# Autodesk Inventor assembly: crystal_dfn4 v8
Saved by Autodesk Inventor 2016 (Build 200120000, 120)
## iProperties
Created: 2016-09
Part Number: crystal_dfn4 v8
Document SubType Name: Assembly
Designer: Administrator
Author: Administrator
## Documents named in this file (5)
- c:\worker\convert-fusion-aug-2016\tmp\job-1\19\output\files\b1646d38-3d95-4128-a552-c87d2d1b62c9\crystal_dfn4 v8.iam
- c:\worker\convert-fusion-aug-2016\tmp\job-1\19\output\files\b1646d38-3d95-4128-a552-c87d2d1b62c9\Component38.ipt
- c:\worker\convert-fusion-aug-2016\tmp\job-1\19\output\files\b1646d38-3d95-4128-a552-c87d2d1b62c9\Component39.ipt
- c:\worker\convert-fusion-aug-2016\tmp\job-1\19\output\files\b1646d38-3d95-4128-a552-c87d2d1b62c9\Component40.ipt
- c:\worker\convert-fusion-aug-2016\tmp\job-1\19\output\files\b1646d38-3d95-4128-a552-c87d2d1b62c9\Component41.ipt
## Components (4 placed, 4 different names)
1. Component38:1
2. Component39:1
3. Component40:1
4. Component41:1
